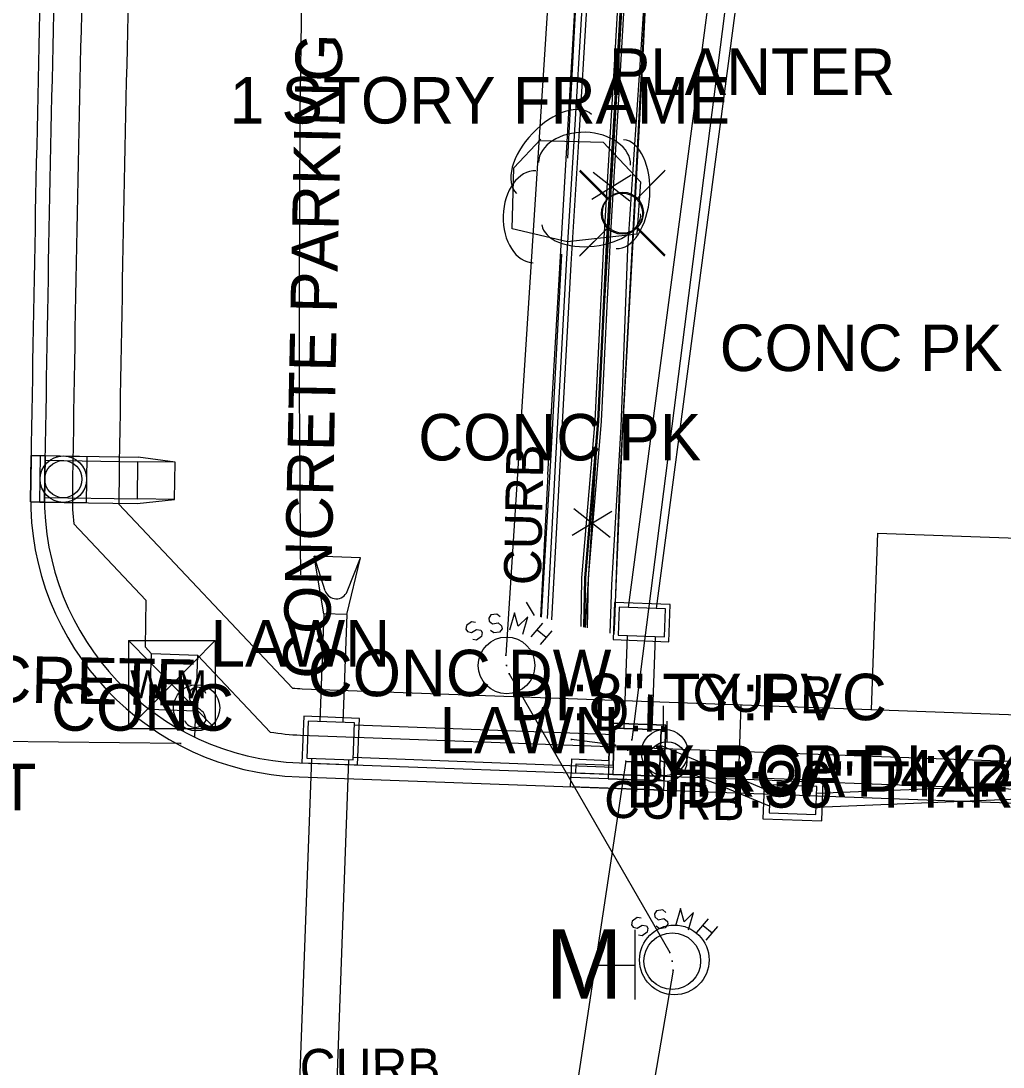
# Model space of a CAD drawing. Extents: x 978516 to 993312, y 1836504 to 1846212.
# Drawn here: x 992490.2 to 992595.9, y 1842600.5 to 1842713.1 of the extents above; entities that cross this region are included whole.
import ezdxf

# ---------------------------------------------------------------- set-up
doc = ezdxf.new("R2010")
doc.units = 0
for name, color, linetype in [('Driveways', 7, 'Continuous'), ('R_Drainage', 7, 'Continuous'), ('R_Proposed Road', 7, 'Continuous'), ('R_Special Ditch', 7, 'Continuous'), ('S_CATCH_BASIN_ANNOT', 7, 'Continuous'), ('S_CURB', 7, 'Continuous'), ('S_CURB_ANNOT', 7, 'Continuous'), ('S_DRG_PT_SYM', 7, 'Continuous'), ('S_DROP_INLET_ANNOT', 7, 'Continuous'), ('S_FENCE', 7, 'Continuous'), ('S_GAS_UTILITIES', 7, 'Continuous'), ('S_MANHOLE', 7, 'Continuous'), ('S_PARKING', 7, 'Continuous'), ('S_PARKING_ANNOT', 7, 'Continuous'), ('S_SANITARY_SEWER', 7, 'Continuous'), ('S_SANITARY_SEWER_ANNOT', 7, 'Continuous'), ('S_SIDEWALK', 7, 'Continuous'), ('S_SIGN', 7, 'Continuous'), ('S_STORM_SEWER', 7, 'Continuous'), ('S_STORM_SEWER_ANNOT', 7, 'Continuous'), ('S_SURVEY_TEXT_ANNOT', 7, 'Continuous'), ('S_TREE', 7, 'Continuous'), ('S_UTILITY_POLE', 7, 'Continuous'), ('S_UTILITY_POLE_ANNOT', 7, 'Continuous'), ('S_UTL_PT_SYM', 7, 'Continuous'), ('S_WALL', 7, 'Continuous'), ('S_WATER_UTILITIES', 7, 'Continuous')]:
    doc.layers.add(name, color=color, linetype=linetype)

msp = doc.modelspace()

# ---------------------------------------------------------------- linework, layer by layer
at = {"layer": 'Driveways'}
for p, q in [((992582.39, 1842657.97), (992581.7, 1842638.98)), ((992582.39, 1842657.97), (992606.37, 1842657.09)), ((992567.7, 1842639.49), (992567.36, 1842630))]:
    msp.add_line(p, q, dxfattribs=at)
at = {"layer": 'R_Drainage'}
for p, q in [((992578.46, 1842823.53), (992555.57, 1842649.95)), ((992581.48, 1842823.44), (992558.58, 1842649.84)), ((992492.8, 1842666.3), (992491.3, 1842666.32)), ((992492.22, 1842661.31), (992492.3, 1842666.31)), ((992492.3, 1842666.31), (992502.8, 1842666.15)), ((992492.73, 1842661.8), (992492.79, 1842665.8)), ((992492.79, 1842665.8), (992502.79, 1842665.65)), ((992497.3, 1842666.23), (992497.22, 1842661.23)), ((992502.73, 1842661.65), (992502.79, 1842665.65)), ((992506.79, 1842665.6), (992502.79, 1842665.65)), ((992506.79, 1842665.6), (992502.8, 1842666.15)), ((992506.73, 1842661.6), (992506.79, 1842665.6)), ((992492.22, 1842661.31), (992502.72, 1842661.15)), ((992492.73, 1842661.8), (992502.73, 1842661.65)), ((992502.72, 1842661.15), (992506.73, 1842661.6)), ((992506.73, 1842661.6), (992502.73, 1842661.65)), ((992526.76, 1842655.3), (992521.77, 1842655.48)), ((992522.79, 1842649.29), (992521.77, 1842655.48)), ((992522.96, 1842651.76), (992521.77, 1842655.48)), ((992525.29, 1842649.2), (992526.76, 1842655.3)), ((992525.31, 1842651.67), (992526.76, 1842655.3)), ((992522.79, 1842649.29), (992522.36, 1842637.68)), ((992525.29, 1842649.2), (992522.79, 1842649.29)), ((992525.29, 1842649.2), (992524.85, 1842637.59)), ((992555.47, 1842646.95), (992555.1, 1842636.95)), ((992558.47, 1842646.84), (992558.1, 1842636.84)), ((992554.08, 1842636.24), (992526.1, 1842637.29)), ((992570.84, 1842630.17), (992559.04, 1842635.11)), ((992521.47, 1842633.71), (992520.14, 1842597.44)), ((992525.46, 1842633.57), (992524.13, 1842597.3)), ((992553.95, 1842632.74), (992525.97, 1842633.8)), ((992570.78, 1842628.57), (992558.98, 1842633.51)), ((992621.45, 1842631.77), (992575.83, 1842629.94)), ((992621.4, 1842630.27), (992575.78, 1842628.44))]:
    msp.add_line(p, q, dxfattribs=at)
for points in [[(992492.8, 1842666.3), (992492.72, 1842661.3), (992491.22, 1842661.32), (992491.3, 1842666.32)], [(992497.3, 1842666.23), (992497.22, 1842661.23), (992492.22, 1842661.31), (992492.3, 1842666.31)], [(992560.09, 1842650.28), (992554.1, 1842650.5), (992553.95, 1842646.5), (992559.95, 1842646.28)], [(992560.09, 1842650.28), (992554.1, 1842650.5), (992553.95, 1842646.5), (992559.95, 1842646.28)], [(992559.58, 1842649.8), (992554.58, 1842649.98), (992554.47, 1842646.98), (992559.47, 1842646.8)], [(992559.58, 1842649.8), (992554.58, 1842649.98), (992554.47, 1842646.98), (992559.47, 1842646.8)], [(992520.63, 1842638.25), (992520.45, 1842633.25), (992526.44, 1842633.03), (992526.63, 1842638.03)], [(992520.63, 1842638.25), (992520.45, 1842633.25), (992526.44, 1842633.03), (992526.63, 1842638.03)], [(992521.11, 1842637.73), (992520.97, 1842633.73), (992525.96, 1842633.55), (992526.11, 1842637.55)], [(992521.11, 1842637.73), (992520.97, 1842633.73), (992525.96, 1842633.55), (992526.11, 1842637.55)], [(992559.62, 1842637.29), (992553.62, 1842637.51), (992553.4, 1842631.51), (992559.4, 1842631.29)], [(992559.62, 1842637.29), (992553.62, 1842637.51), (992553.4, 1842631.51), (992559.4, 1842631.29)], [(992559.1, 1842636.81), (992554.1, 1842636.99), (992553.92, 1842631.99), (992558.92, 1842631.81)], [(992559.1, 1842636.81), (992554.1, 1842636.99), (992553.92, 1842631.99), (992558.92, 1842631.81)], [(992549.42, 1842632.16), (992559.42, 1842631.79), (992559.36, 1842630.29), (992549.37, 1842630.66)], [(992576.55, 1842631.33), (992570.22, 1842631.56), (992570.06, 1842627.23), (992576.39, 1842627)], [(992576.55, 1842631.33), (992570.22, 1842631.56), (992570.06, 1842627.23), (992576.39, 1842627)], [(992575.86, 1842630.69), (992570.86, 1842630.87), (992570.75, 1842627.87), (992575.75, 1842627.69)], [(992575.86, 1842630.69), (992570.86, 1842630.87), (992570.75, 1842627.87), (992575.75, 1842627.69)]]:
    msp.add_lwpolyline(points, close=True, dxfattribs=at)
for points in [[(992491.3, 1842666.32), (992491.22, 1842661.32), (992492.72, 1842661.3), (992492.8, 1842666.3)], [(992553.48, 1842633.51), (992553.62, 1842637.51), (992559.62, 1842637.29), (992559.4, 1842631.29), (992554.4, 1842631.48)], [(992553.96, 1842632.99), (992554.1, 1842636.99), (992559.1, 1842636.81), (992558.92, 1842631.81), (992553.92, 1842631.99)], [(992554.4, 1842631.48), (992549.41, 1842631.66), (992549.48, 1842633.66), (992553.48, 1842633.51)], [(992553.92, 1842631.99), (992549.92, 1842632.14), (992549.96, 1842633.14), (992553.96, 1842632.99)]]:
    msp.add_lwpolyline(points, dxfattribs=at)
for radius in [2.5, 2.5, 2.5, 2, 2, 2]:
    msp.add_circle((992494.76, 1842663.77), radius, dxfattribs=at)
msp.add_arc((992524.15, 1842652.14), 1.25, 197.7094, 338.0712, dxfattribs=at)
at = {"layer": 'R_Proposed Road'}
for p, q in [((992500.74, 1842661.09), (992519.44, 1842641.29)), ((992495.88, 1842658.96), (992503.64, 1842650.74)), ((992503.64, 1842650.74), (992503.58, 1842645.74)), ((992503.58, 1842645.74), (992504.25, 1842644.98)), ((992504.03, 1842638.99), (992504.25, 1842644.98)), ((992509.24, 1842644.8), (992504.25, 1842644.98)), ((992508.92, 1842636.01), (992509.24, 1842644.8)), ((992509.24, 1842644.8), (992517.03, 1842636.56)), ((992520.48, 1842641.22), (992673.63, 1842635.61)), ((992509.03, 1842638.81), (992504.03, 1842638.99)), ((992520.3, 1842636.23), (992673.45, 1842630.62)), ((992520.19, 1842633.23), (992673.34, 1842627.62)), ((992520.14, 1842631.73), (992673.29, 1842626.12))]:
    msp.add_line(p, q, dxfattribs=at)
for centre, radius, start, end in [((998202.23, 1842580.69), 5711.58, 178.03611, 179.18294), ((998202.23, 1842580.69), 5710.08, 178.03611, 179.18294), ((998202.23, 1842580.69), 5707.08, 178.03611, 179.18294), ((998202.23, 1842580.69), 5702.08, 178.03611, 179.18294), ((992521.23, 1842661.71), 30, 179.1829, 267.9024), ((992521.23, 1842661.71), 28.5, 179.1829, 267.9024), ((992521.23, 1842661.71), 25.5, 179.1829, 186.1988), ((992521.23, 1842661.71), 20.5, 179.1829, 181.7279), ((992521.23, 1842661.71), 20.5, 264.974, 267.9024), ((992521.23, 1842661.71), 25.5, 260.5031, 267.9024)]:
    msp.add_arc(centre, radius, start, end, dxfattribs=at)
at = {"layer": 'R_Special Ditch'}
msp.add_lwpolyline([(992520.34, 1842653.49), (992520.3, 1842656.8), (992520.24, 1842663.41), (992520.19, 1842673.33), (992520.18, 1842683.25), (992520.2, 1842693.17), (992520.27, 1842703.09), (992520.38, 1842713.01), (992520.53, 1842722.92), (992520.72, 1842732.84), (992520.83, 1842737.8), (992520.95, 1842742.76), (992521.23, 1842752.68), (992521.53, 1842762.59), (992521.85, 1842772.51), (992522.18, 1842782.48), (992522.52, 1842792.47), (992522.85, 1842802.46), (992523.19, 1842812.46), (992523.53, 1842822.45), (992523.86, 1842832.45), (992523.86, 1842832.45)], dxfattribs=at)
at = {"layer": 'S_CURB'}
for points in [[(992546.86, 1842648.77), (992547.74, 1842665.27), (992548.93, 1842686.92), (992549.78, 1842700.72), (992550.62, 1842714.51), (992551.82, 1842735.84), (992553.02, 1842757.18), (992553.78, 1842769.94), (992554.54, 1842782.69), (992555.27, 1842795.19), (992556, 1842807.69), (992556.53, 1842821.07)], [(992547.35, 1842648.65), (992548.24, 1842665.25), (992549.43, 1842686.9), (992550.28, 1842700.69), (992551.12, 1842714.48), (992552.32, 1842735.81), (992553.52, 1842757.15), (992554.28, 1842769.91), (992555.04, 1842782.66), (992555.77, 1842795.17), (992556.5, 1842807.67), (992557.03, 1842821.05)], [(992545.47, 1842649.09), (992544.6, 1842650.53)]]:
    msp.add_lwpolyline(points, dxfattribs=at)
at = {"layer": 'S_DRG_PT_SYM'}
msp.add_lwpolyline([(992555.52, 1842634.61), (992555.52, 1842634.66), (992555.52, 1842634.61), (992555.47, 1842634.61), (992555.52, 1842634.61), (992555.52, 1842634.56), (992555.52, 1842634.61), (992555.57, 1842634.61)], dxfattribs=at)
at = {"layer": 'S_FENCE'}
for p, q in [((992554.45, 1842707.71), (992555.3, 1842722.76)), ((992553.37, 1842689.69), (992554.45, 1842707.71)), ((992551.64, 1842693.92), (992555.9, 1842696.54)), ((992555.73, 1842693.68), (992551.81, 1842696.78)), ((992552.39, 1842670.02), (992553.37, 1842689.69)), ((992550.99, 1842653.12), (992552.39, 1842670.02)), ((992549.53, 1842657.73), (992553.8, 1842660.33)), ((992553.62, 1842657.48), (992549.71, 1842660.59)), ((992550.89, 1842647.83), (992550.99, 1842653.12))]:
    msp.add_line(p, q, dxfattribs=at)
for points in [[(992552.49, 1842673.27), (992561.75, 1842831.71)], [(992553.89, 1842697.22), (992555.06, 1842717.19)], [(992552.49, 1842673.27), (992553.66, 1842693.23)], [(992550.96, 1842647.81), (992552.54, 1842672.98)], [(992551.79, 1842661.02), (992552.54, 1842672.98)], [(992550.96, 1842647.81), (992551.54, 1842657.04)]]:
    msp.add_lwpolyline(points, dxfattribs=at)
at = {"layer": 'S_GAS_UTILITIES'}
msp.add_line((992507.38, 1842635.34), (992463.05, 1842635.77), dxfattribs=at)
at = {"layer": 'S_MANHOLE'}
for p, q in [((992556.33, 1842607.76), (992556.33, 1842615.26)), ((992552.15, 1842611.47), (992556.33, 1842611.47))]:
    msp.add_line(p, q, dxfattribs=at)
msp.add_circle((992560.53, 1842612.03), 3.75, dxfattribs=at)
at = {"layer": 'S_PARKING'}
for points in [[(992540.72, 1842840.22), (992547.57, 1842833.51), (992555.58, 1842824.79), (992556.18, 1842824.25), (992555.08, 1842806.76), (992554.31, 1842792.69), (992553.53, 1842778.62), (992552.54, 1842763.48), (992551.55, 1842748.35), (992550.38, 1842724.29), (992549.71, 1842711.3), (992549.04, 1842698.32)], [(992546.92, 1842664.26), (992549.81, 1842714.29), (992552.98, 1842764.57), (992553.72, 1842809.95), (992554.49, 1842829.89), (992540.81, 1842840.22)], [(992564.22, 1842829.85), (992562.83, 1842805.95), (992562.09, 1842793.27), (992561.35, 1842780.58), (992560.48, 1842766.3), (992559.6, 1842752.02), (992569.69, 1842751.71), (992570.98, 1842751.16), (992572.11, 1842749.95), (992572.43, 1842748.26), (992571.58, 1842746.73), (992569.73, 1842746.08), (992559.27, 1842746.41), (992558.35, 1842732.56), (992557.03, 1842708.92), (992555.79, 1842685.03), (992554.58, 1842662.63), (992554.1, 1842648.42), (992554.03, 1842647.1)], [(992554.96, 1842668.42), (992557.08, 1842707.1), (992558.91, 1842746.04), (992569.81, 1842745.82)], [(992548.37, 1842687.98), (992547.23, 1842666.38), (992546.21, 1842648.92)], [(992554.06, 1842647.1), (992554.96, 1842668.42)], [(992546.92, 1842664.26), (992546.13, 1842648.94)]]:
    msp.add_lwpolyline(points, dxfattribs=at)
at = {"layer": 'S_SANITARY_SEWER'}
for p, q in [((992554.96, 1842839.73), (992542.4, 1842644.82)), ((992538.15, 1842648.03), (992538.07, 1842647.64)), ((992538.07, 1842647.64), (992538.26, 1842647.37)), ((992538.69, 1842648.42), (992538.15, 1842648.03)), ((992539.11, 1842648.34), (992538.69, 1842648.42)), ((992538.69, 1842647.26), (992539.23, 1842647.61)), ((992539.23, 1842647.61), (992539.7, 1842647.53)), ((992539.7, 1842647.53), (992539.85, 1842647.26)), ((992545.12, 1842646.79), (992546.36, 1842648.26)), ((992545.78, 1842647.57), (992546.75, 1842646.75)), ((992538.26, 1842647.37), (992538.69, 1842647.26)), ((992539.23, 1842646.44), (992538.84, 1842646.52)), ((992539.77, 1842646.83), (992539.23, 1842646.44)), ((992539.85, 1842647.26), (992539.77, 1842646.83)), ((992547.33, 1842647.45), (992546.09, 1842645.98)), ((992542.75, 1842642.83), (992560.04, 1842612.83)), ((992555.99, 1842616.21), (992555.91, 1842615.82)), ((992556.53, 1842616.59), (992555.99, 1842616.21)), ((992556.96, 1842616.52), (992556.53, 1842616.59)), ((992562.96, 1842614.97), (992564.2, 1842616.44)), ((992555.91, 1842615.82), (992556.1, 1842615.55)), ((992556.1, 1842615.55), (992556.53, 1842615.43)), ((992556.53, 1842615.43), (992557.07, 1842615.78)), ((992557.07, 1842615.78), (992557.54, 1842615.7)), ((992557.61, 1842615.01), (992557.07, 1842614.62)), ((992557.54, 1842615.7), (992557.69, 1842615.43)), ((992557.69, 1842615.43), (992557.61, 1842615.01)), ((992563.62, 1842615.74), (992564.59, 1842614.93)), ((992565.17, 1842615.63), (992563.93, 1842614.15)), ((992557.07, 1842614.62), (992556.68, 1842614.7)), ((992560.39, 1842610.92), (992527.83, 1842420.11))]:
    msp.add_line(p, q, dxfattribs=at)
for points in [[(992541.79, 1842648.96), (992541.44, 1842649.23), (992540.78, 1842649.16), (992540.55, 1842648.81), (992540.59, 1842648.5), (992540.94, 1842648.19), (992541.56, 1842648.3), (992541.94, 1842647.99), (992541.98, 1842647.68), (992541.71, 1842647.3), (992541.09, 1842647.22), (992540.74, 1842647.49)], [(992544.23, 1842647.1), (992544.77, 1842648.96), (992543.73, 1842647.95), (992543.34, 1842649.39), (992542.8, 1842647.53)], [(992559.63, 1842617.14), (992559.28, 1842617.41), (992558.62, 1842617.33), (992558.39, 1842616.98), (992558.43, 1842616.67), (992558.78, 1842616.36), (992559.4, 1842616.48), (992559.78, 1842616.17), (992559.82, 1842615.86), (992559.55, 1842615.47), (992558.93, 1842615.39), (992558.58, 1842615.66)], [(992562.07, 1842615.28), (992562.61, 1842617.14), (992561.57, 1842616.13), (992561.18, 1842617.56), (992560.64, 1842615.7)]]:
    msp.add_lwpolyline(points, dxfattribs=at)
for centre in [(992542.47, 1842643.73), (992560.31, 1842611.9)]:
    msp.add_circle(centre, 3.05, dxfattribs=at)
at = {"layer": 'S_SIDEWALK'}
msp.add_lwpolyline([(992553.64, 1842647.18), (992553.81, 1842652.4), (992554.8, 1842669.41), (992555.52, 1842688.56), (992556.81, 1842707.81), (992557.8, 1842722.75), (992558.81, 1842746.44), (992569.53, 1842746.44), (992570.84, 1842746.92), (992571.73, 1842747.93), (992571.9, 1842748.82), (992571.69, 1842749.68), (992571.37, 1842750.26), (992570.84, 1842750.82), (992569.78, 1842751.25), (992559.25, 1842751.87), (992560.88, 1842776.01), (992561.65, 1842788.72), (992562.43, 1842801.43), (992563.33, 1842816.18), (992564.23, 1842830.92)], dxfattribs=at)
at = {"layer": 'S_SIGN'}
msp.add_circle((992509.11, 1842639.16), 2.49, dxfattribs=at)
for centre, radius, start, end in [((992509.8, 1842640.49), 1.5, 167.1196, 241.9813), ((992509.19, 1842640.43), 0.95, 16.5258, 156.8957), ((992508.7, 1842637.82), 1.4, 358.6529, 73.7063), ((992508.96, 1842638.34), 1.28, 204.641, 335.359)]:
    msp.add_arc(centre, radius, start, end, dxfattribs=at)
at = {"layer": 'S_STORM_SEWER'}
for p, q in [((992583.9, 1842855), (992555.95, 1842635.73)), ((992554.18, 1842635.13), (992549.45, 1842635.76)), ((992555.31, 1842633.42), (992549.51, 1842594.97))]:
    msp.add_line(p, q, dxfattribs=at)
at = {"layer": 'S_TREE'}
msp.add_lwpolyline([(992545.97, 1842700.23), (992552.88, 1842700.04), (992556.87, 1842695.76), (992556.49, 1842690.15), (992549.04, 1842689.31), (992543.07, 1842690.73), (992543.25, 1842697.28), (992546.17, 1842700.35)], dxfattribs=at)
for centre, major_axis, ratio in [((992547.59, 1842698.77), (-4.04, -4.25), 0.55008), ((992550.86, 1842697.71), (-4.95, 0.13), 0.685311), ((992554.66, 1842694.45), (0.39, 5.86), 0.55008), ((992545.49, 1842692.02), (-0.14, -4.95), 0.685311), ((992551.59, 1842691.73), (5.31, 0.6), 0.540699)]:
    msp.add_ellipse(centre, major_axis=major_axis, ratio=ratio, start_param=3.141593, end_param=6.283185, dxfattribs=at)
at = {"layer": 'S_UTILITY_POLE'}
for p, q in [((992553.3, 1842693.93), (992550.32, 1842696.91)), ((992553.39, 1842694.03), (992550.41, 1842697.02)), ((992556.48, 1842693.93), (992559.46, 1842696.91)), ((992556.57, 1842694.03), (992559.55, 1842697.02)), ((992553.3, 1842690.75), (992550.32, 1842687.77)), ((992553.39, 1842690.86), (992550.41, 1842687.87)), ((992556.48, 1842690.75), (992559.46, 1842687.77)), ((992556.57, 1842690.86), (992559.55, 1842687.87)), ((992559.35, 1842636.88), (992559.35, 1842639.36)), ((992559.75, 1842635.49), (992559.75, 1842637.74)), ((992557.66, 1842633.36), (992555.33, 1842633.36)), ((992559.83, 1842628.94), (992559.83, 1842631.27))]:
    msp.add_line(p, q, dxfattribs=at)
for centre, radius in [((992554.9, 1842692.35), 2.21), ((992554.99, 1842692.45), 2.21), ((992559.49, 1842634.36), 2.5), ((992559.75, 1842633.38), 2.13)]:
    msp.add_circle(centre, radius, dxfattribs=at)
at = {"layer": 'S_UTL_PT_SYM'}
for points in [[(992542.4, 1842644.82), (992542.4, 1842644.87), (992542.4, 1842644.82), (992542.35, 1842644.82), (992542.4, 1842644.82), (992542.4, 1842644.77), (992542.4, 1842644.82), (992542.45, 1842644.82)], [(992542.47, 1842643.73), (992542.47, 1842643.78), (992542.47, 1842643.73), (992542.42, 1842643.73), (992542.47, 1842643.73), (992542.47, 1842643.68), (992542.47, 1842643.73), (992542.52, 1842643.73)], [(992542.75, 1842642.83), (992542.75, 1842642.88), (992542.75, 1842642.83), (992542.7, 1842642.83), (992542.75, 1842642.83), (992542.75, 1842642.78), (992542.75, 1842642.83), (992542.8, 1842642.83)], [(992507.38, 1842635.34), (992507.38, 1842635.39), (992507.38, 1842635.34), (992507.33, 1842635.34), (992507.38, 1842635.34), (992507.38, 1842635.29), (992507.38, 1842635.34), (992507.43, 1842635.34)], [(992549.45, 1842635.76), (992549.45, 1842635.81), (992549.45, 1842635.76), (992549.4, 1842635.76), (992549.45, 1842635.76), (992549.45, 1842635.71), (992549.45, 1842635.76), (992549.5, 1842635.76)], [(992554.18, 1842635.13), (992554.18, 1842635.18), (992554.18, 1842635.13), (992554.13, 1842635.13), (992554.18, 1842635.13), (992554.18, 1842635.08), (992554.18, 1842635.13), (992554.23, 1842635.13)], [(992555.95, 1842635.73), (992555.95, 1842635.78), (992555.95, 1842635.73), (992555.9, 1842635.73), (992555.95, 1842635.73), (992555.95, 1842635.68), (992555.95, 1842635.73), (992556, 1842635.73)], [(992555.52, 1842634.61), (992555.52, 1842634.66), (992555.52, 1842634.61), (992555.47, 1842634.61), (992555.52, 1842634.61), (992555.52, 1842634.56), (992555.52, 1842634.61), (992555.57, 1842634.61)], [(992555.31, 1842633.42), (992555.31, 1842633.47), (992555.31, 1842633.42), (992555.26, 1842633.42), (992555.31, 1842633.42), (992555.31, 1842633.37), (992555.31, 1842633.42), (992555.36, 1842633.42)], [(992560.04, 1842612.83), (992560.04, 1842612.88), (992560.04, 1842612.83), (992559.99, 1842612.83), (992560.04, 1842612.83), (992560.04, 1842612.78), (992560.04, 1842612.83), (992560.09, 1842612.83)], [(992560.31, 1842611.9), (992560.31, 1842611.95), (992560.31, 1842611.9), (992560.26, 1842611.9), (992560.31, 1842611.9), (992560.31, 1842611.85), (992560.31, 1842611.9), (992560.36, 1842611.9)], [(992560.39, 1842610.92), (992560.39, 1842610.97), (992560.39, 1842610.92), (992560.34, 1842610.92), (992560.39, 1842610.92), (992560.39, 1842610.87), (992560.39, 1842610.92), (992560.44, 1842610.92)]]:
    msp.add_lwpolyline(points, dxfattribs=at)
at = {"layer": 'S_WALL'}
for points in [[(992550.49, 1842647.92), (992550.59, 1842653.14), (992551.99, 1842670.05), (992552.97, 1842689.71), (992554.05, 1842707.73), (992554.9, 1842722.78), (992555.82, 1842737.33), (992556.74, 1842751.88), (992557.36, 1842764.66), (992557.97, 1842777.43), (992559.51, 1842801.17), (992560.54, 1842816.51), (992561.56, 1842831.84)], [(992550.79, 1842647.85), (992550.89, 1842653.12), (992552.29, 1842670.03), (992553.27, 1842689.7), (992554.35, 1842707.71), (992555.2, 1842722.76), (992556.12, 1842737.31), (992557.04, 1842751.87), (992557.66, 1842764.64), (992558.28, 1842777.41), (992559.81, 1842801.15), (992560.83, 1842816.49), (992561.86, 1842831.82)], [(992551.18, 1842647.76), (992551.28, 1842653.1), (992552.69, 1842670), (992553.67, 1842689.68), (992554.75, 1842707.69), (992555.59, 1842722.74), (992556.51, 1842737.29), (992557.43, 1842751.84), (992558.05, 1842764.62), (992558.67, 1842777.39), (992560.21, 1842801.12), (992561.23, 1842816.46), (992562.26, 1842831.79)]]:
    msp.add_lwpolyline(points, dxfattribs=at)
at = {"layer": 'S_WATER_UTILITIES'}
for p, q in [((992501.76, 1842646.42), (992511.1, 1842646.42)), ((992501.76, 1842646.42), (992501.76, 1842636.93)), ((992501.76, 1842646.42), (992511.1, 1842636.93)), ((992511.1, 1842646.42), (992501.76, 1842636.93)), ((992511.1, 1842646.42), (992511.1, 1842636.93)), ((992501.76, 1842636.93), (992511.1, 1842636.93))]:
    msp.add_line(p, q, dxfattribs=at)

# ---------------------------------------------------------------- texts
at = {"layer": 'S_CATCH_BASIN_ANNOT'}
msp.add_text('THROAT 4X.40 BACK THROAT 4X.40', height=5, dxfattribs=at).set_placement((992555.52, 1842629.61))
at = {"layer": 'S_CURB_ANNOT'}
for rotation, p in [(88.8373, (992546.16, 1842652.33)), (358.8373, (992562.44, 1842638.83)), (358.8373, (992552.94, 1842627.34)), (0.2576, (992520.21, 1842598.44))]:
    msp.add_text('CURB', height=4, rotation=rotation, dxfattribs=at).set_placement(p)
at = {"layer": 'S_DROP_INLET_ANNOT'}
msp.add_text('D.I.', height=4, rotation=358.8373, dxfattribs=at).set_placement((992551.76, 1842636.72))
at = {"layer": 'S_MANHOLE'}
msp.add_text('M', height=7.46, dxfattribs=at).set_placement((992546.65, 1842607.85))
at = {"layer": 'S_PARKING_ANNOT'}
for s, height, rotation, p in [('CONCRETE PARKING', 5.0005, 88.8373, (992523.4, 1842642.24)), ('CONCRETE', 5, 358.8373, (992471.6, 1842640.11))]:
    msp.add_text(s, height=height, rotation=rotation, dxfattribs=at).set_placement(p)
at = {"layer": 'S_SANITARY_SEWER_ANNOT'}
msp.add_text('DI:8" TY:PVC', height=5, dxfattribs=at).set_placement((992542.75, 1842637.83))
at = {"layer": 'S_STORM_SEWER_ANNOT'}
for s, p in [('TY:RCP DI:12"', (992554.18, 1842630.13)), ('B DI:36" TY:RCP', (992555.31, 1842628.42))]:
    msp.add_text(s, height=5, dxfattribs=at).set_placement(p)
at = {"layer": 'S_SURVEY_TEXT_ANNOT'}
for s, p in [('PLANTER', (992553.47, 1842705.13)), ('1 STORY FRAME', (992512.67, 1842702.05)), ('CONC PK', (992565.41, 1842675.41)), ('CONC PK', (992532.96, 1842665.79)), ('LAWN', (992510.6, 1842643.6)), ('CONC DW', (992521.07, 1842640.41)), ('CONC', (992493.45, 1842636.7)), ('LAWN', (992535.25, 1842634.26))]:
    msp.add_text(s, height=5, dxfattribs=at).set_placement(p)
at = {"layer": 'S_UTILITY_POLE_ANNOT'}
msp.add_text('ATT', height=5, dxfattribs=at).set_placement((992479.23, 1842628.14))
at = {"layer": 'S_WATER_UTILITIES'}
msp.add_text('W M', height=3, dxfattribs=at).set_placement((992501.96, 1842640.19))

doc.saveas('drawing.dxf')
